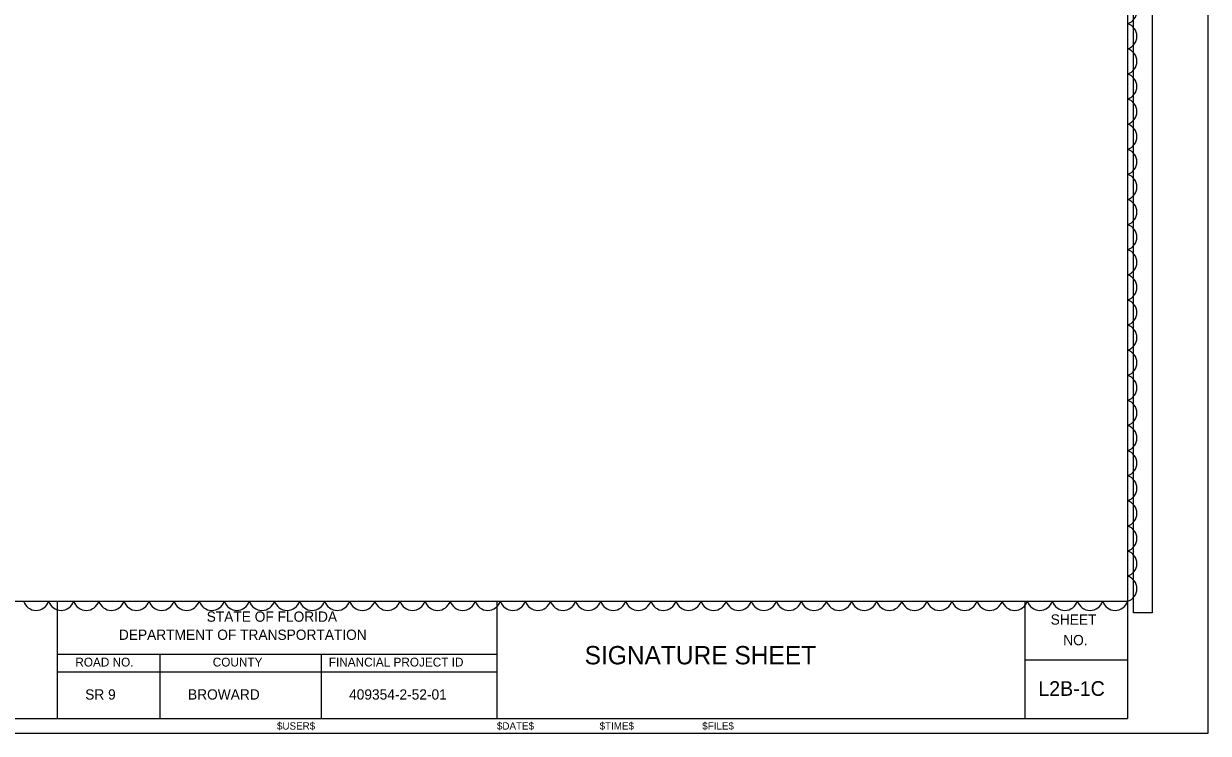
# Model space of a CAD drawing. Extents: x -811.3 to -790.1, y -2211.9 to -2188.9.
# Drawn here: x -802.91 to -794.84, y -2211.94 to -2207.1 of the extents above; entities that cross this region are included whole.
import ezdxf

# ---------------------------------------------------------------- set-up
doc = ezdxf.new("R2010")
doc.units = 0
for name, color, linetype in [('Cloud_dp', 7, 'Continuous'), ('PlotBorder_dp', 7, 'Continuous'), ('ScratchEle_dp', 7, 'Continuous'), ('SheetBorder_dp', 7, 'Continuous'), ('SheetLines_dp', 7, 'Continuous'), ('TextMinor', 7, 'Continuous'), ('TextMisc', 7, 'Continuous'), ('TextShtNo', 7, 'Continuous')]:
    doc.layers.add(name, color=color, linetype=linetype)

msp = doc.modelspace()

# ---------------------------------------------------------------- linework, layer by layer
at = {"layer": 'Cloud_dp'}
for centre, start, end in [((-795.4127, -2207.0187), 287.5, 72.5), ((-795.4127, -2207.1898), 287.5, 72.5), ((-795.4127, -2207.3609), 287.5, 72.5), ((-795.4127, -2207.532), 287.5, 72.5), ((-795.4127, -2207.7032), 287.5, 72.5), ((-795.4127, -2207.8743), 287.5, 72.5), ((-795.4127, -2208.0454), 287.5, 72.5), ((-795.4127, -2208.2165), 287.5, 72.5), ((-795.4127, -2208.3877), 287.5, 72.5), ((-795.4127, -2208.5588), 287.5, 72.5), ((-795.4127, -2208.7299), 287.5, 72.5), ((-795.4127, -2208.901), 287.5, 72.5), ((-795.4127, -2209.0721), 287.5, 72.5), ((-795.4127, -2209.2433), 287.5, 72.5), ((-795.4127, -2209.4144), 287.5, 72.5), ((-795.4127, -2209.5855), 287.5, 72.5), ((-795.4127, -2209.7566), 287.5, 72.5), ((-795.4127, -2209.9278), 287.5, 72.5), ((-795.4127, -2210.0989), 287.5, 72.5), ((-795.4127, -2210.27), 287.5, 72.5), ((-795.4127, -2210.4411), 287.5, 72.5), ((-795.4127, -2210.6122), 287.5, 72.5), ((-795.4127, -2210.7834), 287.5, 72.5), ((-795.4127, -2210.9545), 287.5, 72.5), ((-802.8296, -2211.0131), 197.5, 342.5), ((-802.6585, -2211.0131), 197.5, 342.5), ((-802.4874, -2211.0131), 197.5, 342.5), ((-802.3162, -2211.0131), 197.5, 342.5), ((-802.1451, -2211.0131), 197.5, 342.5), ((-801.974, -2211.0131), 197.5, 342.5), ((-801.8029, -2211.0131), 197.5, 342.5), ((-801.6317, -2211.0131), 197.5, 342.5), ((-801.4606, -2211.0131), 197.5, 342.5), ((-801.2895, -2211.0131), 197.5, 342.5), ((-801.1184, -2211.0131), 197.5, 342.5), ((-800.9472, -2211.0131), 197.5, 342.5), ((-800.7761, -2211.0131), 197.5, 342.5), ((-800.605, -2211.0131), 197.5, 342.5), ((-800.4339, -2211.0131), 197.5, 342.5), ((-800.2628, -2211.0131), 197.5, 342.5), ((-800.0916, -2211.0131), 197.5, 342.5), ((-799.9205, -2211.0131), 197.5, 342.5), ((-799.7494, -2211.0131), 197.5, 342.5), ((-799.5783, -2211.0131), 197.5, 342.5), ((-799.4071, -2211.0131), 197.5, 342.5), ((-799.236, -2211.0131), 197.5, 342.5), ((-799.0649, -2211.0131), 197.5, 342.5), ((-798.8938, -2211.0131), 197.5, 342.5), ((-798.7227, -2211.0131), 197.5, 342.5), ((-798.5515, -2211.0131), 197.5, 342.5), ((-798.3804, -2211.0131), 197.5, 342.5), ((-798.2093, -2211.0131), 197.5, 342.5), ((-798.0382, -2211.0131), 197.5, 342.5), ((-797.867, -2211.0131), 197.5, 342.5), ((-797.6959, -2211.0131), 197.5, 342.5), ((-797.5248, -2211.0131), 197.5, 342.5), ((-797.3537, -2211.0131), 197.5, 342.5), ((-797.1826, -2211.0131), 197.5, 342.5), ((-797.0114, -2211.0131), 197.5, 342.5), ((-796.8403, -2211.0131), 197.5, 342.5), ((-796.6692, -2211.0131), 197.5, 342.5), ((-796.4981, -2211.0131), 197.5, 342.5), ((-796.3269, -2211.0131), 197.5, 342.5), ((-796.1558, -2211.0131), 197.5, 342.5), ((-795.9847, -2211.0131), 197.5, 342.5), ((-795.8136, -2211.0131), 197.5, 342.5), ((-795.6425, -2211.0131), 197.5, 342.5), ((-795.4713, -2211.0131), 197.5, 342.5)]:
    msp.add_arc(centre, 0.0897, start, end, dxfattribs=at)
at = {"layer": 'PlotBorder_dp'}
msp.add_lwpolyline([(-811.3358, -2211.9401), (-794.8358, -2211.9401), (-794.8358, -2201.3401), (-811.3358, -2201.3401)], close=True, dxfattribs=at)
at = {"layer": 'ScratchEle_dp'}
msp.add_lwpolyline([(-795.3456, -2204.2776), (-795.218, -2204.2776), (-795.218, -2211.1195), (-795.3456, -2211.1195)], close=True, dxfattribs=at)
at = {"layer": 'SheetBorder_dp'}
for p, q in [((-795.3858, -2201.4401), (-795.3858, -2211.8401)), ((-810.7858, -2211.0401), (-795.3858, -2211.0401)), ((-810.7858, -2211.8401), (-795.3858, -2211.8401))]:
    msp.add_line(p, q, dxfattribs=at)
at = {"layer": 'SheetLines_dp'}
for p, q in [((-802.6858, -2211.0401), (-802.6858, -2211.8401)), ((-799.6858, -2211.8401), (-799.6858, -2211.0401)), ((-796.0858, -2211.8401), (-796.0858, -2211.0401)), ((-802.6858, -2211.4001), (-799.6858, -2211.4001)), ((-801.9858, -2211.4001), (-801.9858, -2211.8401)), ((-800.8858, -2211.4001), (-800.8858, -2211.8401)), ((-796.0858, -2211.4401), (-795.3858, -2211.4401)), ((-802.6858, -2211.5201), (-799.6858, -2211.5201))]:
    msp.add_line(p, q, dxfattribs=at)

# ---------------------------------------------------------------- texts
at = {"layer": 'TextMinor'}
msp.add_text('$USER$', height=0.05, dxfattribs=at).set_placement((-801.1868, -2211.915))
for s, p in [('$DATE$', (-799.6868, -2211.915)), ('$TIME$', (-798.9868, -2211.915)), ('$FILE$', (-798.2868, -2211.915))]:
    msp.add_text(s, height=0.05, rotation=360, dxfattribs=at).set_placement(p)
at = {"layer": 'TextMisc'}
for s, height, p in [('STATE OF FLORIDA', 0.07, (-801.6664, -2211.1799)), ('DEPARTMENT OF TRANSPORTATION', 0.07, (-802.265, -2211.3035)), ('       SIGNATURE SHEET         ', 0.125, (-799.414, -2211.4703)), ('ROAD NO.', 0.06, (-802.5619, -2211.4849)), ('COUNTY', 0.06, (-801.6248, -2211.4849)), ('FINANCIAL PROJECT ID', 0.06, (-800.8335, -2211.4849)), (' SR 9  ', 0.07, (-802.5207, -2211.7104)), ('  BROWARD   ', 0.07, (-801.8455, -2211.7104)), ('409354-2-52-01', 0.07, (-800.6951, -2211.7104))]:
    msp.add_text(s, height=height, dxfattribs=at).set_placement(p)
for s, p in [('SHEET', (-795.911, -2211.1995)), ('NO.', (-795.8253, -2211.3397))]:
    msp.add_text(s, height=0.07, rotation=359.86066, dxfattribs=at).set_placement(p)
at = {"layer": 'TextShtNo'}
msp.add_text('L2B-1C', height=0.1, dxfattribs=at).set_placement((-795.9952, -2211.6849))

doc.saveas('drawing.dxf')
